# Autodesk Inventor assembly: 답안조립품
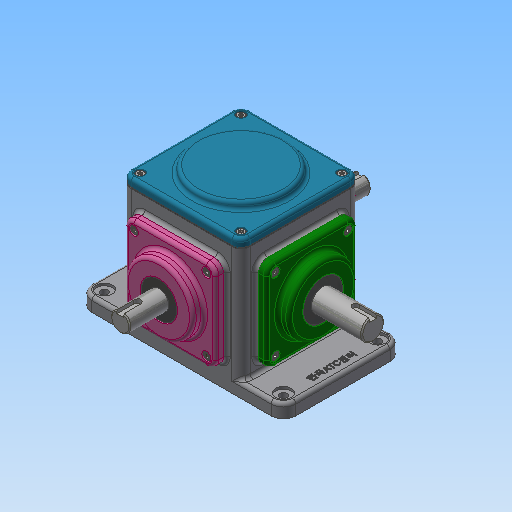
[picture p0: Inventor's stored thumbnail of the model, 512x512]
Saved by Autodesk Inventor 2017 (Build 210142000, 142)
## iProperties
Part Number: 답안조립품
Material: 일반
Document SubType Name: Assembly
Designer: user
Author: user
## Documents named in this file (16)
- C:\Users\MRC\Desktop\620307V1004\620307V1004\답안조립품.iam
- C:\Users\MRC\Desktop\620307V1004\620307V1004\본체.ipt
- C:\Users\MRC\Desktop\620307V1004\620307V1004\개스킷.ipt
- C:\Users\MRC\Desktop\620307V1004\620307V1004\메인베벨기어.ipt
- C:\Users\MRC\Desktop\620307V1004\620307V1004\메인축.ipt
- C:\Users\MRC\Desktop\620307V1004\620307V1004\메인커버.ipt
- C:\Users\MRC\Desktop\620307V1004\620307V1004\베어링 6203.ipt
- C:\Users\MRC\Desktop\620307V1004\620307V1004\베어링 6204.ipt
- C:\Users\MRC\Desktop\620307V1004\620307V1004\볼트 M4.ipt
- C:\Users\MRC\Desktop\620307V1004\620307V1004\상부커버.ipt
- C:\Users\MRC\Desktop\620307V1004\620307V1004\서브베벨기어.ipt
- C:\Users\MRC\Desktop\620307V1004\620307V1004\서브축.ipt
- C:\Users\MRC\Desktop\620307V1004\620307V1004\서브커버.ipt
- C:\Users\MRC\Desktop\620307V1004\620307V1004\오일 실 17 32 8.ipt
- C:\Users\MRC\Desktop\620307V1004\620307V1004\오일 실 20 35 8.ipt
- C:\Users\MRC\Desktop\620307V1004\620307V1004\키 4x4.ipt
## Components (1 placed, 1 different names)
1. 개스킷:1
